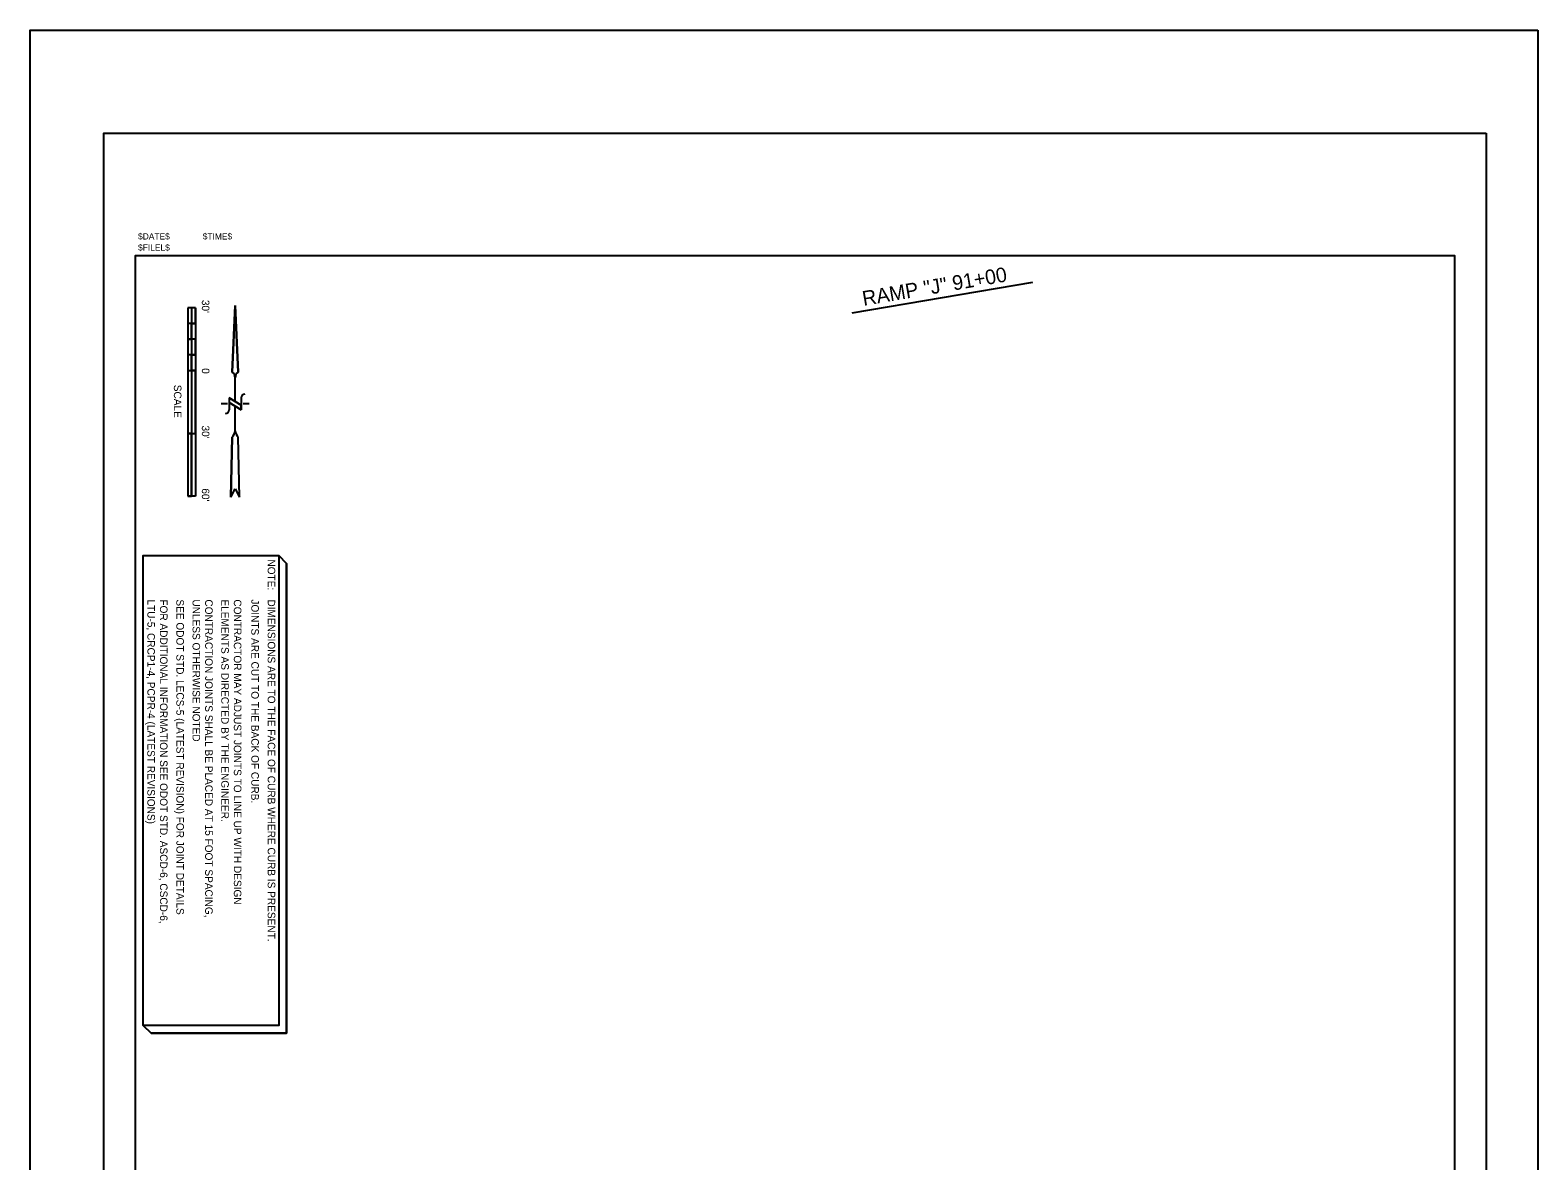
# Model space of a CAD drawing. Extents: x 2150474 to 2151194, y 142872 to 143952.
# Drawn here: x 2150474 to 2151194, y 143412 to 143952 of the extents above; entities that cross this region are included whole.
import ezdxf

# ---------------------------------------------------------------- set-up
doc = ezdxf.new("R2010")
doc.units = 0
for name, color, linetype in [('EX_Align_8_Leader', 7, 'Continuous'), ('PR_Align_1_Leader', 7, 'Continuous'), ('PR_Align_1_PI_Curve', 7, 'Continuous'), ('PR_Align_Ramp_A_PI_Curve', 7, 'Continuous'), ('PR_Align_Ramp_B_PC', 7, 'Continuous'), ('PR_Align_Ramp_B_PI', 7, 'Continuous'), ('PR_Align_Ramp_G', 7, 'Continuous'), ('PR_Align_Ramp_G_Leader', 7, 'Continuous'), ('PR_Align_Ramp_G_Txt', 7, 'Continuous')]:
    doc.layers.add(name, color=color, linetype=linetype)

msp = doc.modelspace()

# ---------------------------------------------------------------- linework, layer by layer
at = {"layer": 'EX_Align_8_Leader'}
msp.add_line((2150952.38, 143831.58), (2150866.02, 143816.9), dxfattribs=at)
at = {"layer": 'PR_Align_1_PI_Curve'}
msp.add_lwpolyline([(2150592.34, 143701.14), (2150592.34, 143476.72), (2150527.66, 143476.72), (2150527.66, 143701.14)], close=True, dxfattribs=at)
msp.add_lwpolyline([(2150592.34, 143701.14), (2150596.09, 143697.39), (2150596.09, 143472.97), (2150531.41, 143472.97), (2150527.66, 143476.72)], dxfattribs=at)
at = {"layer": 'PR_Align_Ramp_A_PI_Curve'}
msp.add_lwpolyline([(2151168.88, 143902.92), (2151168.88, 142882.92), (2150508.88, 142882.92), (2150508.88, 143902.92)], close=True, dxfattribs=at)
at = {"layer": 'PR_Align_Ramp_B_PC'}
for p, q in [((2150552.63, 143819.42), (2150548.88, 143819.42)), ((2150548.88, 143819.42), (2150548.88, 143729.42)), ((2150550.76, 143819.42), (2150550.76, 143811.92)), ((2150552.63, 143819.42), (2150550.76, 143819.42)), ((2150550.76, 143819.42), (2150550.76, 143811.92)), ((2150552.63, 143819.42), (2150552.63, 143729.42)), ((2150552.63, 143811.92), (2150552.63, 143819.42)), ((2150552.63, 143811.92), (2150548.88, 143811.92)), ((2150550.76, 143811.92), (2150548.88, 143811.92)), ((2150548.88, 143811.92), (2150548.88, 143804.42)), ((2150550.76, 143811.92), (2150550.76, 143804.42)), ((2150550.76, 143811.92), (2150552.63, 143811.92)), ((2150550.76, 143804.42), (2150550.76, 143811.92)), ((2150552.63, 143804.42), (2150548.88, 143804.42)), ((2150552.63, 143804.42), (2150548.88, 143804.42)), ((2150548.88, 143804.42), (2150550.76, 143804.42)), ((2150550.76, 143804.42), (2150550.76, 143796.92)), ((2150552.63, 143804.42), (2150550.76, 143804.42)), ((2150550.76, 143804.42), (2150550.76, 143796.92)), ((2150552.63, 143796.92), (2150552.63, 143804.42)), ((2150552.63, 143796.92), (2150548.88, 143796.92)), ((2150550.76, 143796.92), (2150548.88, 143796.92)), ((2150548.88, 143796.92), (2150548.88, 143789.42)), ((2150550.76, 143796.92), (2150550.76, 143789.42)), ((2150550.76, 143796.92), (2150552.63, 143796.92)), ((2150550.76, 143789.42), (2150550.76, 143796.92)), ((2150548.88, 143789.42), (2150550.76, 143789.42)), ((2150548.88, 143789.42), (2150550.76, 143789.42)), ((2150550.76, 143789.42), (2150552.63, 143789.42)), ((2150550.76, 143789.42), (2150550.76, 143729.42)), ((2150552.63, 143789.42), (2150550.76, 143789.42)), ((2150550.76, 143789.42), (2150550.76, 143759.42)), ((2150552.63, 143759.42), (2150552.63, 143789.42)), ((2150548.88, 143759.42), (2150550.76, 143759.42)), ((2150550.76, 143759.42), (2150548.88, 143759.42)), ((2150548.88, 143759.42), (2150548.88, 143729.42)), ((2150550.76, 143759.42), (2150552.63, 143759.42)), ((2150550.76, 143759.42), (2150552.63, 143759.42)), ((2150550.76, 143729.42), (2150550.76, 143759.42)), ((2150550.76, 143729.42), (2150548.88, 143729.42)), ((2150548.88, 143729.42), (2150550.76, 143729.42)), ((2150552.63, 143729.42), (2150550.76, 143729.42))]:
    msp.add_line(p, q, dxfattribs=at)
at = {"layer": 'PR_Align_Ramp_B_PI'}
for p, q in [((2150570.1, 143788.75), (2150571.54, 143820.48)), ((2150571.54, 143820.48), (2150570.1, 143788.75)), ((2150571.54, 143820.48), (2150572.98, 143788.75)), ((2150572.98, 143788.75), (2150571.54, 143820.48)), ((2150571.54, 143774.72), (2150571.54, 143785.94)), ((2150567.8, 143773.57), (2150564.92, 143773.57)), ((2150574.42, 143772.99), (2150568.66, 143776.44)), ((2150568.66, 143776.44), (2150574.42, 143772.99)), ((2150568.66, 143776.44), (2150568.66, 143770.69)), ((2150571.54, 143774.72), (2150568.66, 143776.44)), ((2150568.66, 143776.44), (2150568.66, 143774.14)), ((2150574.42, 143770.69), (2150568.66, 143774.14)), ((2150574.42, 143772.99), (2150571.54, 143774.72)), ((2150571.54, 143760.61), (2150571.54, 143772.41)), ((2150574.42, 143776.44), (2150574.42, 143770.69)), ((2150574.42, 143770.69), (2150574.42, 143772.99)), ((2150578.16, 143773.57), (2150575.28, 143773.57)), ((2150569.53, 143728.95), (2150570.1, 143757.73)), ((2150570.1, 143757.73), (2150569.53, 143728.95)), ((2150573.56, 143728.95), (2150572.98, 143757.73)), ((2150573.56, 143728.95), (2150572.98, 143757.73)), ((2150569.53, 143728.95), (2150571.54, 143732.98)), ((2150569.53, 143728.95), (2150571.54, 143732.98)), ((2150571.54, 143732.98), (2150573.56, 143728.95)), ((2150571.54, 143732.98), (2150573.56, 143728.95))]:
    msp.add_line(p, q, dxfattribs=at)
for points in [[(2150568.66, 143774.14), (2150571.54, 143772.41), (2150574.42, 143770.69)], [(2150571.54, 143760.61), (2150571.54, 143760.61), (2150571.54, 143760.61)]]:
    msp.add_lwpolyline(points, dxfattribs=at)
for centre, radius, start, end in [((2150568.09, 143785.94), 3.45, 360, 54.38016), ((2150568.09, 143785.94), 3.45, 360, 54.38016), ((2150574.99, 143785.94), 3.45, 125.61984, 180), ((2150574.99, 143785.94), 3.45, 125.61984, 180), ((2150576.15, 143776.44), 1.73, 90, 180), ((2150566.93, 143770.69), 1.73, 270, 0), ((2150566.53, 143761.31), 5.06, 314.95671, 352.41889), ((2150566.53, 143761.31), 5.06, 314.95671, 352.059), ((2150576.55, 143761.31), 5.06, 187.58111, 225.04329), ((2150576.55, 143761.31), 5.06, 187.941, 225.04329)]:
    msp.add_arc(centre, radius, start, end, dxfattribs=at)
at = {"layer": 'PR_Align_Ramp_G'}
msp.add_line((2150596.09, 143697.39), (2150592.34, 143701.14), dxfattribs=at)
for points in [[(2150592.34, 143701.14), (2150592.34, 143476.72), (2150527.66, 143476.72)], [(2150527.66, 143476.72), (2150531.41, 143472.97), (2150596.09, 143472.97), (2150596.09, 143697.39)]]:
    msp.add_lwpolyline(points, dxfattribs=at)
at = {"layer": 'PR_Align_Ramp_G_Leader'}
msp.add_lwpolyline([(2151193.63, 143952.04), (2151193.63, 142872.04), (2150473.63, 142872.04), (2150473.63, 143952.04)], close=True, dxfattribs=at)
at = {"layer": 'PR_Align_Ramp_G_Txt'}
msp.add_lwpolyline([(2150523.88, 142899.42), (2150523.88, 143844.42), (2151153.88, 143844.42), (2151153.88, 142899.42)], close=True, dxfattribs=at)

# ---------------------------------------------------------------- texts
at = {"layer": 'PR_Align_1_Leader'}
for s, p in [('$DATE$', (2150525.16, 143852.06)), ('$FILEL$', (2150525.16, 143846.74)), ('$TIME$', (2150556.05, 143852.06))]:
    msp.add_text(s, height=3, rotation=360, dxfattribs=at).set_placement(p)
at = {"layer": 'PR_Align_1_PI_Curve'}
for s, height, rotation, p in [('RAMP "J" 91+00', 7, 9.67898, (2150871.66, 143820.36)), ('NOTE:', 3.6, 270, (2150587.08, 143699.28)), ('LTU-5, CRCP1-4, PCPR-4 (LATEST REVISIONS)', 3.6, 270, (2150529.62, 143680.18)), ('FOR ADDITIONAL INFORMATION SEE ODOT STD. ASCD-6, CSCD-6,', 3.6, 270, (2150535.63, 143680.18)), ('SEE ODOT STD. LECS-5 (LATEST REVISION) FOR JOINT DETAILS', 3.6, 270, (2150543.47, 143680.18)), ('UNLESS OTHERWISE NOTED', 3.6, 270, (2150551.19, 143680.18)), ('CONTRACTION JOINTS SHALL BE PLACED AT 15 FOOT SPACING,', 3.6, 270, (2150557.2, 143680.18)), ('ELEMENTS AS DIRECTED BY THE ENGINEER.', 3.6, 270, (2150564.9, 143680.18)), ('CONTRACTOR MAY ADJUST JOINTS TO LINE UP WITH DESIGN', 3.6, 270, (2150570.91, 143680.18)), ('JOINTS ARE CUT TO THE BACK OF CURB.', 3.6, 270, (2150579.25, 143680.18)), ('DIMENSIONS ARE TO THE FACE OF CURB WHERE CURB IS PRESENT.', 3.6, 270, (2150587.08, 143680.18))]:
    msp.add_text(s, height=height, rotation=rotation, dxfattribs=at).set_placement(p)
at = {"layer": 'PR_Align_Ramp_B_PC'}
for s, p in [("30'", (2150555.63, 143823.23)), ('0', (2150555.63, 143790.6)), ('SCALE', (2150542.28, 143782.68)), ("30'", (2150555.63, 143763.23)), ("60'", (2150555.63, 143733.23))]:
    msp.add_text(s, height=3.6, rotation=270, dxfattribs=at).set_placement(p)

doc.saveas('drawing.dxf')
